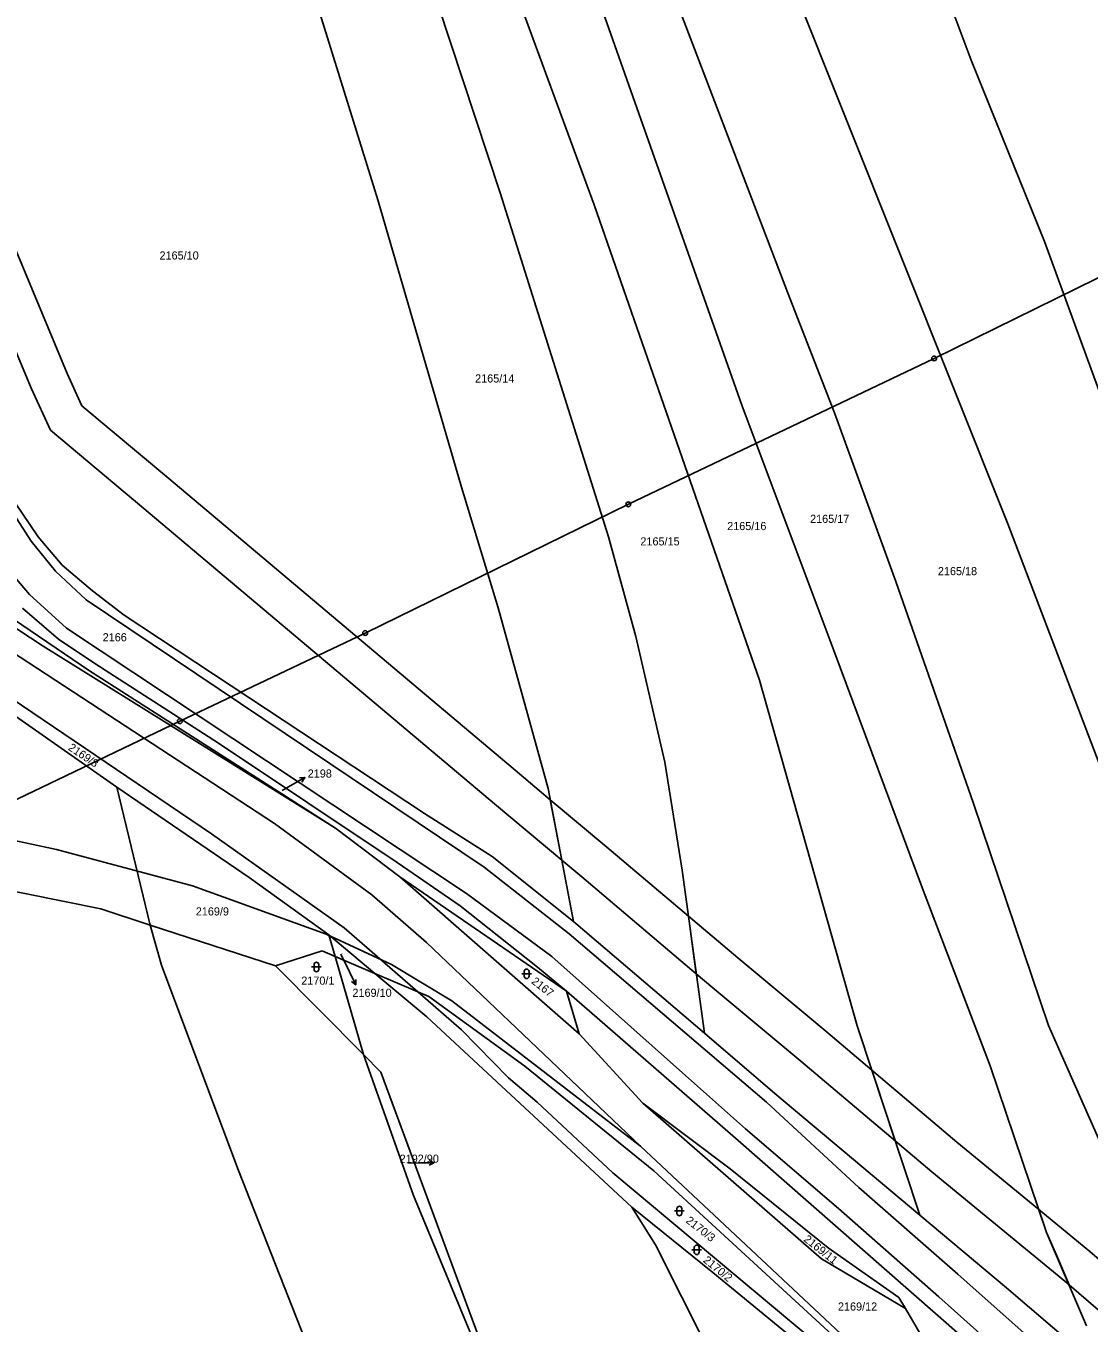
# Model space of a CAD drawing. Extents: x -785744 to -782822, y -1067550 to -1063910.
# Drawn here: x -784823 to -784600.3, y -1065048.4 to -1064776.7 of the extents above; entities that cross this region are included whole.
import ezdxf

# ---------------------------------------------------------------- set-up
doc = ezdxf.new("R2010")
doc.units = 0
for name, color, linetype in [('Hranice parcel', 7, 'Continuous'), ('Parcelní čísla', 7, 'Continuous'), ('Pop_ČP_popisy', 7, 'Continuous'), ('Poz_předměty', 7, 'Continuous'), ('Vnitřní kresba', 7, 'Continuous'), ('Věcná břemena k části', 7, 'Continuous'), ('Značky kultur', 7, 'Continuous')]:
    doc.layers.add(name, color=color, linetype=linetype)

msp = doc.modelspace()

# ---------------------------------------------------------------- linework, layer by layer
at = {"layer": 'Hranice parcel'}
for points in [[(-784701.85, -1064731.97), (-784663.48, -1064832.45)], [(-784714.98, -1064737.24), (-784689.64, -1064809.07)], [(-784641.12, -1064740.79), (-784624.99, -1064783.89)], [(-784744.45, -1064748.65), (-784723.65, -1064811.69)], [(-784766.87, -1064756.43), (-784749.25, -1064813.16)], [(-784721.24, -1064767.09), (-784703.94, -1064814.21)], [(-784662.39, -1064768.06), (-784617.3, -1064881.01)], [(-784624.99, -1064783.89), (-784609.62, -1064821.85)], [(-784689.64, -1064809.07), (-784673.04, -1064856.13)], [(-784723.65, -1064811.69), (-784700.94, -1064883.73)], [(-784749.25, -1064813.16), (-784731.71, -1064873.32)], [(-784703.94, -1064814.21), (-784669.35, -1064913.71)], [(-784609.62, -1064821.85), (-784597.19, -1064855.84)], [(-784663.48, -1064832.45), (-784653.62, -1064857.75)], [(-784673.04, -1064856.13), (-784653.73, -1064907.52)], [(-784653.62, -1064857.75), (-784640.75, -1064893.07)], [(-784731.71, -1064873.32), (-784724.06, -1064898.6)], [(-784825.38, -1064876.41), (-784820.43, -1064883.72)], [(-784883.48, -1064878.68), (-784784.14, -1064945.95)], [(-784884.07, -1064880.1), (-784803.95, -1064936.13)], [(-784617.3, -1064881.01), (-784590.01, -1064952.6)], [(-784820.43, -1064883.72), (-784815.41, -1064889.68)], [(-784700.94, -1064883.73), (-784695.21, -1064904.58)], [(-784851.08, -1064885.79), (-784819.37, -1064906.65)], [(-784841.59, -1064890.13), (-784809.7, -1064911.76)], [(-784815.41, -1064889.68), (-784809.07, -1064895.03)], [(-784640.75, -1064893.07), (-784624.5, -1064939.6)], [(-784809.07, -1064895.03), (-784802.44, -1064900.15)], [(-784823.73, -1064898.63), (-784816.19, -1064905.17)], [(-784724.06, -1064898.6), (-784713.6, -1064936.41)], [(-784802.44, -1064900.15), (-784776.29, -1064917.37)], [(-784819.37, -1064906.65), (-784758.12, -1064944.72)], [(-784816.19, -1064905.17), (-784808.58, -1064910.27)], [(-784695.21, -1064904.58), (-784689.12, -1064930.93)], [(-784653.73, -1064907.52), (-784635.2, -1064957.34)], [(-784809.7, -1064911.76), (-784758.12, -1064944.72)], [(-784808.58, -1064910.27), (-784782.66, -1064926.96)], [(-784669.35, -1064913.71), (-784648.87, -1064986.1)], [(-784776.29, -1064917.37), (-784739.46, -1064941.66)], [(-784782.66, -1064926.96), (-784745.21, -1064951.92)], [(-784689.12, -1064930.93), (-784685.53, -1064953.52)], [(-784803.95, -1064936.13), (-784796.97, -1064965.02)], [(-784803.95, -1064936.13), (-784776.21, -1064955.04)], [(-784713.6, -1064936.41), (-784708.26, -1064964.28)], [(-784739.46, -1064941.66), (-784725.3, -1064950.7)], [(-784624.5, -1064939.6), (-784608.76, -1064986.08)], [(-784758.12, -1064944.72), (-784744.69, -1064954.93)], [(-784784.14, -1064945.95), (-784756.32, -1064965.63)], [(-784853.39, -1064952.34), (-784807.28, -1064961.66)], [(-784745.21, -1064951.92), (-784732.05, -1064961.01)], [(-784725.3, -1064950.7), (-784708.26, -1064964.28)], [(-784776.21, -1064955.04), (-784759.51, -1064967.1)], [(-784744.69, -1064954.93), (-784707.09, -1064987.83)], [(-784744.69, -1064954.93), (-784709.76, -1064978.84)], [(-784685.53, -1064953.52), (-784680.85, -1064987.69)], [(-784635.2, -1064957.34), (-784620.98, -1064994.51)], [(-784732.05, -1064961.01), (-784715.83, -1064973.87)], [(-784807.28, -1064961.66), (-784796.97, -1064965.02)], [(-784796.97, -1064965.02), (-784770.7, -1064973.58)], [(-784796.97, -1064965.02), (-784794.6, -1064973.42)], [(-784756.32, -1064965.63), (-784740.9, -1064979.02)], [(-784708.26, -1064964.28), (-784707.76, -1064964.68)], [(-784707.76, -1064964.68), (-784680.85, -1064987.69)], [(-784759.51, -1064967.1), (-784749.87, -1064975.18)], [(-784759.51, -1064967.1), (-784758.21, -1064971.62)], [(-784770.7, -1064973.58), (-784760.95, -1064970.45)], [(-784760.95, -1064970.45), (-784758.21, -1064971.62)], [(-784758.21, -1064971.62), (-784749.87, -1064975.18)], [(-784758.21, -1064971.62), (-784752.3, -1064992.12)], [(-784794.6, -1064973.42), (-784778.61, -1065016.05)], [(-784770.7, -1064973.58), (-784752.3, -1064992.12)], [(-784715.83, -1064973.87), (-784709.76, -1064978.84)], [(-784749.87, -1064975.18), (-784740.9, -1064979.02)], [(-784749.87, -1064975.18), (-784739.04, -1064984.27)], [(-784740.9, -1064979.02), (-784738.57, -1064980.02)], [(-784740.9, -1064979.02), (-784731.72, -1064986.98)], [(-784738.57, -1064980.02), (-784718.5, -1064994.59)], [(-784709.76, -1064978.84), (-784707.09, -1064987.83)], [(-784709.76, -1064978.84), (-784674.34, -1065009.68)], [(-784739.04, -1064984.27), (-784696.06, -1065024.1)], [(-784731.72, -1064986.98), (-784721.87, -1064997.03)], [(-784707.09, -1064987.83), (-784693.75, -1065002.31)], [(-784680.85, -1064987.69), (-784666.08, -1065000.33)], [(-784648.87, -1064986.1), (-784635.7, -1065025.8)], [(-784608.76, -1064986.08), (-784587.53, -1065033.99)], [(-784752.3, -1064992.12), (-784748.62, -1064995.83)], [(-784752.3, -1064992.12), (-784741.79, -1065021.68)], [(-784748.62, -1064995.83), (-784716.52, -1065082.68)], [(-784718.5, -1064994.59), (-784691.47, -1065016.5)], [(-784620.98, -1064994.51), (-784609.16, -1065029.44)], [(-784721.87, -1064997.03), (-784715.9, -1065002.1)], [(-784666.08, -1065000.33), (-784635.7, -1065025.8)], [(-784715.9, -1065002.1), (-784700.04, -1065016.92)], [(-784693.75, -1065002.31), (-784675.45, -1065016.07)], [(-784693.75, -1065002.31), (-784656.32, -1065034.95)], [(-784674.34, -1065009.68), (-784621.66, -1065055.78)], [(-784778.61, -1065016.05), (-784757.54, -1065069.65)], [(-784700.04, -1065016.92), (-784649.32, -1065059.26)], [(-784691.47, -1065016.5), (-784652.27, -1065052.55)], [(-784675.45, -1065016.07), (-784654.96, -1065032.63)], [(-784741.79, -1065021.68), (-784716.52, -1065082.68)], [(-784696.06, -1065024.1), (-784679.12, -1065037.76)], [(-784696.06, -1065024.1), (-784691.13, -1065031.98)], [(-784635.7, -1065025.8), (-784617.57, -1065041)], [(-784609.16, -1065029.44), (-784600.8, -1065048.94)], [(-784691.13, -1065031.98), (-784680.17, -1065053.75)], [(-784654.96, -1065032.63), (-784640.13, -1065043.01)], [(-784656.32, -1065034.95), (-784638.76, -1065045.36)], [(-784679.12, -1065037.76), (-784655.64, -1065057.06)], [(-784617.57, -1065041), (-784593.5, -1065061.6)], [(-784640.13, -1065043.01), (-784638.76, -1065045.36)], [(-784638.76, -1065045.36), (-784626.27, -1065066.7)]]:
    msp.add_lwpolyline(points, dxfattribs=at)
at = {"layer": 'Pop_ČP_popisy'}
for p, q in [((-784767.17, -1064935.62), (-784764.56, -1064934.14)), ((-784755.21, -1064974.84), (-784753.91, -1064977.55)), ((-784740.52, -1065014.85), (-784737.52, -1065014.8))]:
    msp.add_line(p, q, dxfattribs=at)
for points in [[(-784765.68, -1064934.2), (-784764.56, -1064934.14), (-784765.18, -1064935.07)], [(-784769.34, -1064936.85), (-784767.17, -1064935.62)], [(-784757, -1064971.1), (-784755.21, -1064974.84)], [(-784753.89, -1064976.43), (-784753.91, -1064977.55), (-784754.8, -1064976.86)], [(-784743, -1065014.9), (-784740.52, -1065014.85)], [(-784738.53, -1065014.31), (-784737.52, -1065014.8), (-784738.51, -1065015.31)]]:
    msp.add_lwpolyline(points, dxfattribs=at)
at = {"layer": 'Poz_předměty'}
for points in [[(-784568.8, -1064814.98), (-784632.72, -1064846.35)], [(-784632.72, -1064846.35), (-784696.79, -1064876.91)], [(-784696.79, -1064876.91), (-784751.93, -1064903.87)], [(-784770.95, -1064943.74), (-784846.26, -1064894.55)], [(-784751.93, -1064903.87), (-784790.75, -1064922.32)], [(-784790.75, -1064922.32), (-784860.46, -1064955.72)], [(-784770.95, -1064943.74), (-784750.55, -1064958.69)], [(-784816.57, -1064949.2), (-784831.68, -1064946.02)], [(-784788.07, -1064956.84), (-784816.57, -1064949.2)], [(-784760.07, -1064966.92), (-784788.07, -1064956.84)], [(-784750.55, -1064958.69), (-784739.08, -1064968.66)], [(-784746.39, -1064973.29), (-784760.07, -1064966.92)], [(-784739.08, -1064968.66), (-784694.26, -1065011.35)], [(-784733.79, -1064980.9), (-784746.39, -1064973.29)], [(-784694.26, -1065011.35), (-784733.79, -1064980.9)], [(-784694.26, -1065011.35), (-784588.33, -1065110.53)]]:
    msp.add_lwpolyline(points, dxfattribs=at)
for centre in [(-784632.72, -1064846.35), (-784696.79, -1064876.91), (-784751.93, -1064903.87), (-784790.75, -1064922.32)]:
    msp.add_circle(centre, 0.5, dxfattribs=at)
at = {"layer": 'Vnitřní kresba'}
for points in [[(-784828.77, -1064874.06), (-784821.86, -1064884.6)], [(-784821.86, -1064884.6), (-784816.82, -1064890.94)], [(-784828.13, -1064888.9), (-784822.25, -1064895.83)], [(-784816.82, -1064890.94), (-784810.35, -1064896.91)], [(-784822.25, -1064895.83), (-784814.47, -1064902.82)], [(-784810.35, -1064896.91), (-784727, -1064952.93)], [(-784814.47, -1064902.82), (-784730.72, -1064958.39)], [(-784727, -1064952.93), (-784709.22, -1064966.85)], [(-784730.72, -1064958.39), (-784712.79, -1064971.64)], [(-784709.22, -1064966.85), (-784667.84, -1065002.11)], [(-784712.79, -1064971.64), (-784685.44, -1064995.99)], [(-784685.44, -1064995.99), (-784672.28, -1065007.68)], [(-784667.84, -1065002.11), (-784648.5, -1065020.02)], [(-784672.28, -1065007.68), (-784652.79, -1065024.42)], [(-784648.5, -1065020.02), (-784627.75, -1065038.14)], [(-784652.79, -1065024.42), (-784631.78, -1065042.92)], [(-784627.75, -1065038.14), (-784601.33, -1065061.67)], [(-784631.78, -1065042.92), (-784605.52, -1065066.37)]]:
    msp.add_lwpolyline(points, dxfattribs=at)
at = {"layer": 'Věcná břemena k části'}
for points in [[(-784814.33, -1064849.48), (-784832.88, -1064805.21)], [(-784840.38, -1064808.39), (-784821.81, -1064852.74)], [(-784811.25, -1064856.27), (-784814.33, -1064849.48)], [(-784821.81, -1064852.74), (-784817.87, -1064861.35)], [(-784793.08, -1064871.53), (-784811.25, -1064856.27)], [(-784817.87, -1064861.35), (-784798.32, -1064877.77)], [(-784719.62, -1064933.38), (-784793.08, -1064871.53)], [(-784798.32, -1064877.77), (-784724.86, -1064939.62)], [(-784713.14, -1064938.8), (-784719.62, -1064933.38)], [(-784701.29, -1064948.72), (-784713.14, -1064938.8)], [(-784713.14, -1064938.8), (-784710.72, -1064951.45), (-784706.55, -1064954.94)], [(-784712.25, -1064943.46), (-784713.14, -1064938.8)], [(-784724.86, -1064939.62), (-784710.72, -1064951.45)], [(-784711.61, -1064946.79), (-784712.25, -1064943.46)], [(-784710.72, -1064951.45), (-784711.61, -1064946.79)], [(-784684.21, -1064963.17), (-784701.29, -1064948.72)], [(-784706.55, -1064954.94), (-784682.55, -1064975.25)], [(-784645.78, -1064995.43), (-784655.43, -1064987.27), (-784673.87, -1064971.92), (-784684.21, -1064963.17)], [(-784684.21, -1064963.17), (-784682.55, -1064975.25), (-784679.11, -1064978.16)], [(-784682.55, -1064975.25), (-784684.21, -1064963.17)], [(-784679.11, -1064978.16), (-784660.67, -1064993.51), (-784640.86, -1065010.25)], [(-784627.97, -1065010.47), (-784645.78, -1064995.43), (-784640.86, -1065010.25)], [(-784640.86, -1065010.25), (-784645.78, -1064995.43)], [(-784640.86, -1065010.25), (-784633.19, -1065016.73)], [(-784610.8, -1065024.59), (-784627.97, -1065010.47)], [(-784633.19, -1065016.73), (-784605.38, -1065039.59), (-784604.47, -1065040.38)], [(-784604.47, -1065040.38), (-784607.06, -1065034.33), (-784608.91, -1065030.02), (-784609.16, -1065029.44), (-784610.8, -1065024.59)], [(-784590.98, -1065041.27), (-784600.12, -1065033.37), (-784610.8, -1065024.59)], [(-784610.8, -1065024.59), (-784609.16, -1065029.44), (-784604.47, -1065040.38), (-784596.36, -1065047.39)]]:
    msp.add_lwpolyline(points, dxfattribs=at)
at = {"layer": 'Značky kultur'}
for p, q in [((-784763.14, -1064973.81), (-784761.14, -1064973.81)), ((-784762.64, -1064974.31), (-784762.64, -1064973.31)), ((-784761.64, -1064973.31), (-784761.64, -1064974.31)), ((-784718.6, -1064975.74), (-784718.6, -1064974.74)), ((-784717.6, -1064974.74), (-784717.6, -1064975.74)), ((-784719.1, -1064975.24), (-784717.1, -1064975.24)), ((-784687.1, -1065024.91), (-784685.1, -1065024.91)), ((-784686.6, -1065025.41), (-784686.6, -1065024.41)), ((-784685.6, -1065024.41), (-784685.6, -1065025.41)), ((-784683.47, -1065033.04), (-784681.47, -1065033.04)), ((-784682.97, -1065033.54), (-784682.97, -1065032.54)), ((-784681.97, -1065032.54), (-784681.97, -1065033.54))]:
    msp.add_line(p, q, dxfattribs=at)
for centre, start, end in [((-784762.14, -1064973.31), 0, 180), ((-784762.14, -1064974.31), 180, 0), ((-784718.1, -1064974.74), 0, 180), ((-784718.1, -1064975.74), 180, 0), ((-784686.1, -1065024.41), 0, 180), ((-784686.1, -1065025.41), 180, 0), ((-784682.47, -1065032.54), 0, 180), ((-784682.47, -1065033.54), 180, 0)]:
    msp.add_arc(centre, 0.5, start, end, dxfattribs=at)

# ---------------------------------------------------------------- texts
at = {"layer": 'Parcelní čísla'}
for s, height, p in [('2165/10', 1.7, (-784795.01, -1064825.64)), ('2165/14', 1.7, (-784728.89, -1064851.4)), ('2165/17', 1.7, (-784658.72, -1064880.8)), ('2165/16', 1.7, (-784676.09, -1064882.31)), ('2165/15', 1.7, (-784694.27, -1064885.52)), ('2165/18', 1.7, (-784631.95, -1064891.75)), ('2198', 0.1, (-784769.34, -1064936.85)), ('2169/9', 1.7, (-784787.41, -1064963.02)), ('2169/10', 0.1, (-784757, -1064971.1)), ('2170/1', 1.7, (-784765.31, -1064977.52)), ('2192/90', 0.1, (-784743, -1065014.9)), ('2169/12', 1.7, (-784652.88, -1065045.76))]:
    msp.add_text(s, height=height, dxfattribs=at).set_placement(p)
for s, rotation, p in [('2169/8', 326.0702, (-784814.28, -1064928.23)), ('2167', 322.0055, (-784717.24, -1064977.1)), ('2170/3', 322.047, (-784684.9, -1065027.2)), ('2169/11', 321.5607, (-784660.21, -1065031.09)), ('2170/2', 320.8882, (-784681.25, -1065035.47))]:
    msp.add_text(s, height=1.7, rotation=rotation, dxfattribs=at).set_placement(p)
at = {"layer": 'Pop_ČP_popisy'}
for s, p in [('2166', (-784806.92, -1064905.6)), ('2198', (-784763.96, -1064934.14)), ('2169/10', (-784754.59, -1064980.06)), ('2192/90', (-784744.7, -1065014.8))]:
    msp.add_text(s, height=1.7, dxfattribs=at).set_placement(p)

doc.saveas('drawing.dxf')
